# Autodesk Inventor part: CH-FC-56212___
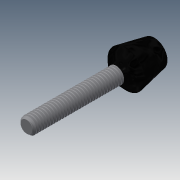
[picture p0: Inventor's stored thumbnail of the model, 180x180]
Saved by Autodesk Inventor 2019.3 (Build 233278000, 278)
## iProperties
Created: 2010-06
Part Number: CH-FC-56212___
Material: Ogólny
Document SubType Name: Modeling
Designer: CADENGINEERING4
Density: 1 g/cm^3
Appearance: Domyślna
Author: CADENGINEERING4
Revision Number: ANY
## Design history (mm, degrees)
feature "NONE"
node "Bryła1"
